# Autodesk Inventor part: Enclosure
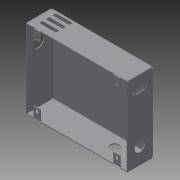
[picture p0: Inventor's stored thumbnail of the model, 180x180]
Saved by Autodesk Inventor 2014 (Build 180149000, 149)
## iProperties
Shininess: 64.0
Length Units: 11272
Angle Units: 11279
Time Units: 11290
Mass Units: 11286
Length Display Precision: 3
Angle Display Precision: 2
Compacted: True
Part Number: Enclosure
Document SubType Name: Sheet Metal
Created: 2003-06
Designer: t_enrig
Manufacturer: Standard
Standards Organization: Custom
Density: 1 g/cm^3
Sheet Metal Rule: Default
Mass: 92.97 g
Surface Area: 1248.56 cm^2
Volume: 92.97 cm^3
Material: Generic
Appearance: Default
Density: 0.0
Volumn: 0.0
Area: 0.0
PropertySet Name: Model Information
Control State: 0
Master: False
Checked Out: False
Author: t_enrig
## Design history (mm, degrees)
node "Face1"
  sketch "Sketch1"
    geometry: L1 (61.481, 5.185)-(251.981, 5.185); L2 (251.981, 5.185)-(251.981, 152.505); L3 (251.981, 152.505)-(61.481, 152.505); L4 (61.481, 152.505)-(61.481, 5.185)
    constraints: 8 end point, 2 parallel, 1 horizontal, 1 perpendicular
    dimensions: "d0" = 190.5 distance of L1.start L1.end; "d1" = 147.32 distance of L3.end L1.start
node "Flange1"
node "Flange2"
node "Flange3"
node "Flange4"
feature "Corner1" dims "d31" = 2.54, "d32" = 1.524 (= BendRadius), "d33" = 0.254, "d34" = 0, "Thickness" = 1.524
feature "Corner2" dims "d35" = 0.254, "d36" = 1.524 (= BendRadius), "d37" = 0.254, "d38" = 0, "Thickness" = 1.524
feature "Corner3" dims "d39" = 0.254, "d40" = 1.524 (= BendRadius), "d41" = 0.254, "d42" = 0, "Thickness" = 1.524
feature "Corner4" dims "d43" = 0.254, "d44" = 1.524 (= BendRadius), "d45" = 0.254, "d46" = 0, "Thickness" = 1.524
sketch "Sketch6"
  geometry: L1 (4.572, 0)-(6.096, 0); L2 (12.446, 1.524)-(12.446, 1.524); L3 (12.446, 0)-(12.446, -19.05); L4 (25.146, -19.05)-(25.146, 0); L5 (-0.254, 1.524)-(-0.254, -148.844); L6 (12.446, -19.05)-(25.146, -19.05); L7 (0, 0)-(189.992, 0) reference; L8 (12.446, 0)-(25.146, 0); C1 r 3.175 at (18.796, -12.7); 2 further points
  constraints: 14 end point, 3 perpendicular, 3 point on line, 1 centre point, 1 collinear, 1 midpoint
  dimensions: "d47" = 12.7 distance between parallel lines of L3 L4; "d48" = 12.7 distance between parallel lines of L3 L5; "d49" = 19.05 distance between parallel lines of L6 L1; "d77" = 6.35 diameter of C1; "d79" = 6.35 distance from line of C1.centre L3; "d80" = 12.7 distance from line of C1.centre L1
extrude "Extrusion1" join sketch "Sketch6" distance "d50" = 1.524; taper "d51" = 0 deg
workplane "Work Plane1"
mirror "Mirror1"
workplane "Work Plane2"
mirror "Mirror2"
bend "Bend6" dims "d57" = 0.762, "d58" = 0.254, "d59" = 2.54, "d60" = 1.524 (= BendRadius), "d61" = 1.524 (= BendRadius), "SeamGap" = 0.00508, "Thickness" = 1.524
bend "Bend7" dims "d62" = 0.762, "d63" = 0.254, "d64" = 2.54, "d65" = 1.524 (= BendRadius), "d66" = 1.524 (= BendRadius), "SeamGap" = 0.00508, "Thickness" = 1.524
bend "Bend8" dims "d67" = 0.762, "d68" = 0.254, "d69" = 2.54, "d70" = 1.524 (= BendRadius), "d71" = 1.524 (= BendRadius), "SeamGap" = 0.00508, "Thickness" = 1.524
bend "Bend9" dims "d72" = 0.762, "d73" = 0.254, "d74" = 2.54, "d75" = 1.524 (= BendRadius), "d76" = 1.524 (= BendRadius), "SeamGap" = 0.00508, "Thickness" = 1.524
sketch "Sketch7"
  geometry: L1 (0, -3.048)-(-47.752, -3.048) reference; L2 (-23.876, 117.094)-(-23.876, 126.746); L3 (-33.295, 121.006)-(-32.748, 124.105); L4 (-33.35, 116.494)-(-33.35, 126.757); L5 (-14.457, 121.006)-(-15.004, 124.105); L6 (-29.693, 116.713)-(-18.059, 116.713); L7 (-23.876, 121.92)-(-25.391, 121.92); L8 (-29.146, 127.127)-(-18.606, 127.127); L9 (-47.752, 147.32)-(0, 147.32) reference; C1 r 10.262 at (-23.876, 28.702); C2 r 1.524 at (-36.373, 121.92); C3 r 1.524 at (-11.379, 121.92); A1 r 3.658 centre (-18.059, 120.371) between (-18.059, 116.713) and (-14.457, 121.006); A2 r 3.658 centre (-29.693, 120.371) between (-33.295, 121.006) and (-29.693, 116.713); A3 r 3.658 centre (-29.146, 123.469) between (-29.146, 127.127) and (-32.748, 124.105); A4 r 3.658 centre (-18.606, 123.469) between (-15.004, 124.105) and (-18.606, 127.127); 3 further points
  constraints: 14 end point, 8 point on circle, 7 centre point, 6 symmetric about line, 6 tangent, 3 midpoint, 2 parallel, 2 vertical alignment, 1 horizontal alignment, 1 other
  dimensions: "d81" = 20.5232 diameter of C1; "d82" = 31.75 distance from line of C1.centre L1; "d98" = 3.048 diameter of C2; "d100" = 24.9936 diameter of C2.centre L2; "d116" = 18.9484 diameter of L4 L2; "d119" = 10.414 diameter of L6 L7; "d121" = 25.4 distance from line of L9 C2.centre
cut "Cut1" sketch "Sketch7" dims "d83" = 1.524 (= Thickness), "d84" = 0
sketch "Sketch8"
  geometry: L1 (41.402, -9.652)-(9.652, -9.652); L2 (9.652, -9.652)-(9.652, -3.302); L3 (9.652, -3.302)-(41.402, -3.302); L4 (41.402, -3.302)-(41.402, -9.652); L5 (0, 3.048)-(187.452, 3.048) reference; L6 (-3.048, 0)-(-3.048, -47.752) reference
  constraints: 8 end point, 2 parallel, 1 horizontal, 1 perpendicular
  dimensions: "d85" = 31.75 distance of L2.end L3.end; "d86" = 6.35 distance of L1.end L2.end; "d87" = 12.7 distance between parallel lines of L1 L5; "d88" = 12.7 distance between parallel lines of L6 L2
cut "Cut2" sketch "Sketch8" dims "d89" = 1.524 (= Thickness), "d90" = 0
pattern_linear "Rectangular Pattern1" dims "d93" = 12.7
sketch "Sketch9"
  geometry: A1 r 8.7 centre (138.1, 19.495) between (146.799, 19.494) and (129.4, 19.495) reference; A2 r 8.7 centre (138.1, 19.495) between (129.4, 19.495) and (146.799, 19.494) reference
extrude "Extrusion2" cut sketch "Sketch9" stored distance "d94" = 25.4; taper "d95" = 0 deg
sketch "Sketch11"
  geometry: A1 r 10.262 centre (25.121, 108.687) between (25.121, 98.425) and (25.121, 118.948) reference; A2 r 10.262 centre (25.121, 108.687) between (25.121, 118.948) and (25.121, 98.425) reference
extrude "Extrusion3" cut sketch "Sketch11" stored distance "d96" = 25.4; taper "d97" = 0 deg
body "Solid1"
face "Plate1" dims "Thickness" = 1.524
sketch "Sketch2"
  geometry: L1 through (-73.66, 0) direction (-1, 0); L2 (-147.32, 0)-(-147.32, 50.8); L3 (-147.32, 50.8)-(0, 50.8); L4 through (0, 25.4) direction (0, -1)
  constraints: 6 end point, 1 horizontal, 1 perpendicular, 1 vertical
face "Plate2" dims "d3" = 1.524 (= BendReliefWidth), "d5" = 3.048 (= MinimumRemnant), "d7" = 50.8, "d8" = 90 deg, "d9" = 1.524, "Thickness" = 1.524
bend "Bend1" dims "d3" = 1.524 (= BendReliefWidth), "d4" = 0.762 (= BendReliefDepth), "d5" = 3.048 (= MinimumRemnant), "d6" = 1.524 (= BendRadius), "d7" = 50.8, "d8" = 90 deg, "d9" = 1.524, "SeamGap" = 0.00508, "Thickness" = 1.524
sketch "Sketch3"
  geometry: L1 through (-94.488, 0) direction (-1, -1.03e-33); L2 (-188.976, 0)-(-188.976, 50.8); L3 (-188.976, 50.8)-(0, 50.8); L4 through (0, 25.4) direction (6.11e-33, -1)
  constraints: 6 end point, 1 horizontal, 1 perpendicular, 1 vertical
face "Plate3" dims "d10" = 1.524 (= BendReliefWidth), "d12" = 3.048 (= MinimumRemnant), "d14" = 50.8, "d15" = 90 deg, "d16" = 1.524, "Thickness" = 1.524
bend "Bend2" dims "d10" = 1.524 (= BendReliefWidth), "d11" = 0.762 (= BendReliefDepth), "d12" = 3.048 (= MinimumRemnant), "d13" = 1.524 (= BendRadius), "d14" = 50.8, "d15" = 90 deg, "d16" = 1.524, "SeamGap" = 0.00508, "Thickness" = 1.524
sketch "Sketch4"
  geometry: L1 through (-94.488, 0) direction (-1, 1.38e-34); L2 (-188.976, 0)-(-188.976, 50.8); L3 (-188.976, 50.8)-(0, 50.8); L4 through (0, 25.4) direction (0, -1)
  constraints: 6 end point, 1 horizontal, 1 perpendicular, 1 vertical
face "Plate4" dims "d17" = 1.524 (= BendReliefWidth), "d19" = 3.048 (= MinimumRemnant), "d21" = 50.8, "d22" = 90 deg, "d23" = 1.524, "Thickness" = 1.524
bend "Bend3" dims "d17" = 1.524 (= BendReliefWidth), "d18" = 0.762 (= BendReliefDepth), "d19" = 3.048 (= MinimumRemnant), "d20" = 1.524 (= BendRadius), "d21" = 50.8, "d22" = 90 deg, "d23" = 1.524, "SeamGap" = 0.00508, "Thickness" = 1.524
sketch "Sketch5"
  geometry: L1 through (-72.136, 0) direction (-1, 3.54e-33); L2 (-144.272, 0)-(-144.272, 50.8); L3 (-144.272, 50.8)-(0, 50.8); L4 through (0, 25.4) direction (0, -1)
  constraints: 6 end point, 1 horizontal, 1 perpendicular, 1 vertical
face "Plate5" dims "d24" = 1.524 (= BendReliefWidth), "d26" = 3.048 (= MinimumRemnant), "d28" = 50.8, "d29" = 90 deg, "d30" = 1.524, "Thickness" = 1.524
bend "Bend4" dims "d24" = 1.524 (= BendReliefWidth), "d25" = 0.762 (= BendReliefDepth), "d26" = 3.048 (= MinimumRemnant), "d27" = 1.524 (= BendRadius), "d28" = 50.8, "d29" = 90 deg, "d30" = 1.524, "SeamGap" = 0.00508, "Thickness" = 1.524
node "Reference1"
node "Reference2"
node "Reference6"
node "Reference7"
other parameters: "BendRadius" = 1.524 (= Thickness), "BendReliefWidth" = 1.524 (= Thickness), "BendReliefDepth" = 0.762 (= 0.5 x Thickness), "CornerReliefSize" = 6.096 (= 4 x Thickness), "MinimumRemnant" = 3.048 (= 2 x Thickness), "TransitionRadius" = 1.524 (= BendRadius), "d2" = 1.524 (= BendRadius), "JacobiRadiusSize" = 1.524 (= Thickness), "d114" = 7.3152, "d115" = 5.2832, "GapSize" = 1.524 (= Thickness)
